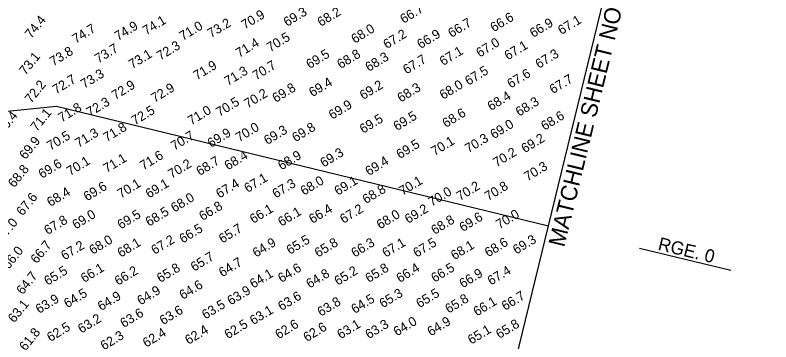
# Model space of a CAD drawing. Extents: x 401290 to 405690, y 1190598 to 1193998.
# Drawn here: x 404273 to 405078, y 1191942 to 1192291 of the extents above; entities that cross this region are included whole.
import ezdxf

# ---------------------------------------------------------------- set-up
doc = ezdxf.new("R2010")
doc.units = 0
for name, color, linetype in [('C-CHAN-POIT', 7, 'Continuous'), ('V-ALGN-TEXT', 7, 'Continuous'), ('V-ANNO-MATC', 7, 'Continuous'), ('V-ANNO-MATC-IDEN', 7, 'Continuous'), ('V-TOPO-SOUN', 7, 'Continuous')]:
    doc.layers.add(name, color=color, linetype=linetype)

msp = doc.modelspace()

# ---------------------------------------------------------------- linework, layer by layer
at = {"layer": 'C-CHAN-POIT'}
for p, q in [((402579.39, 1192009.5), (404317.15, 1192193.7)), ((404317.15, 1192193.7), (404840.85, 1192065.98))]:
    msp.add_line(p, q, dxfattribs=at)
at = {"layer": 'V-ALGN-TEXT'}
msp.add_line((404938, 1192042.28), (405035.16, 1192018.59), dxfattribs=at)
at = {"layer": 'V-ANNO-MATC'}
msp.add_line((404692.33, 1191456.98), (405077.78, 1193037.5), dxfattribs=at)

# ---------------------------------------------------------------- texts
at = {"layer": 'V-ALGN-TEXT'}
msp.add_text('RGE. 0', height=13.92, rotation=346.29456, dxfattribs=at).set_placement((404956.72, 1192040.59))
at = {"layer": 'V-ANNO-MATC-IDEN'}
msp.add_text('MATCHLINE SHEET NO. 025 STA. 6+00 EGMONT CUT-2', height=17.52, rotation=76.29456, dxfattribs=at).set_placement((404857.67, 1192042.53))
at = {"layer": 'V-TOPO-SOUN'}
for s, rotation, p in [('69.3 ', 31.2939, (404562.67, 1192278.04)), ('68.2 ', 31.2939, (404598.66, 1192278.04)), ('66.7 ', 31.2939, (404686.75, 1192281.29)), ('74.4 ', 51.05, (404290.2, 1192265.01)), ('74.1 ', 31.2939, (404412.67, 1192269.02)), ('70.9 ', 31.2939, (404517.69, 1192275.03)), ('66.6 ', 31.2939, (404782.75, 1192272.3)), ('67.1 ', 31.2939, (404854.77, 1192269.32)), ('74.7 ', 31.2939, (404337.67, 1192260.03)), ('74.9 ', 31.2939, (404382.69, 1192263.02)), ('71.0 ', 31.2939, (404451.68, 1192263.02)), ('73.2 ', 31.2939, (404481.67, 1192266.04)), ('68.0 ', 31.2939, (404634.69, 1192260.03)), ('66.7 ', 31.2939, (404737.77, 1192266.3)), ('66.9 ', 31.2939, (404824.78, 1192266.3)), ('70.5 ', 31.2939, (404544.66, 1192251.04)), ('67.2 ', 31.2939, (404668.77, 1192254.32)), ('66.9 ', 31.2939, (404704.77, 1192254.32)), ('71.4 ', 31.2939, (404511.69, 1192245.04)), ('67.0 ', 31.2939, (404767.76, 1192245.3)), ('73.8 ', 31.2939, (404313.69, 1192236.02)), ('73.7 ', 31.2939, (404361.69, 1192239.04)), ('72.3 ', 31.2939, (404427.67, 1192242.02)), ('67.1 ', 31.2939, (404728.78, 1192236.31)), ('67.1 ', 31.2939, (404797.78, 1192242.32)), ('73.1 ', 51.05, (404284.19, 1192226.04)), ('73.1 ', 31.2939, (404397.68, 1192233.03)), ('69.5 ', 31.2939, (404586.69, 1192233.03)), ('68.8 ', 31.2939, (404619.66, 1192233.03)), ('68.3 ', 31.2939, (404649.68, 1192230.05)), ('67.7 ', 31.2939, (404689.77, 1192227.32)), ('67.3 ', 31.2939, (404830.78, 1192233.29)), ('71.9 ', 31.2939, (404466.68, 1192221.02)), ('70.7 ', 31.2939, (404529.67, 1192221.02)), ('73.3 ', 31.2939, (404346.66, 1192212.03)), ('71.3 ', 31.2939, (404499.68, 1192215.02)), ('67.5 ', 31.2939, (404755.78, 1192215.31)), ('67.6 ', 31.2939, (404800.76, 1192212.3)), ('72.7 ', 31.2939, (404316.68, 1192206.03)), ('69.4 ', 31.2939, (404589.67, 1192203.04)), ('67.7 ', 31.2939, (404845.78, 1192206.29)), ('72.2 ', 51.05, (404290.2, 1192196.02)), ('72.9 ', 31.2939, (404379.67, 1192200.03)), ('72.9 ', 31.2939, (404421.66, 1192197.04)), ('69.8 ', 31.2939, (404550.66, 1192197.04)), ('69.2 ', 31.2939, (404643.68, 1192200.03)), ('68.3 ', 31.2939, (404683.77, 1192197.3)), ('68.0 ', 31.2939, (404728.78, 1192200.32)), ('70.2 ', 31.2939, (404520.68, 1192191.04)), ('68.4 ', 31.2939, (404779.77, 1192188.31)), ('72.3 ', 31.2939, (404352.67, 1192182.01)), ('70.5 ', 31.2939, (404490.69, 1192182.01)), ('69.9 ', 31.2939, (404610.67, 1192179.03)), ('68.3 ', 31.2939, (404809.75, 1192182.31)), ('71.8 ', 31.2939, (404322.68, 1192176.04)), ('72.5 ', 31.2939, (404400.66, 1192173.02)), ('71.0 ', 31.2939, (404460.67, 1192173.02)), ('68.6 ', 31.2939, (404731.77, 1192170.3)), ('70.4 ', 51.05, (404260.18, 1192163.01)), ('71.1 ', 51.05, (404296.2, 1192166.03)), ('69.5 ', 31.2939, (404643.68, 1192164.04)), ('69.5 ', 31.2939, (404679.67, 1192167.02)), ('68.6 ', 31.2939, (404836.75, 1192167.32)), ('71.8 ', 31.2939, (404370.68, 1192155.05)), ('70.0 ', 31.2939, (404511.69, 1192155.05)), ('69.8 ', 31.2939, (404571.66, 1192155.05)), ('69.0 ', 31.2939, (404782.75, 1192158.29)), ('70.5 ', 31.2939, (404310.67, 1192146.02)), ('71.3 ', 31.2939, (404340.69, 1192149.04)), ('70.7 ', 31.2939, (404442.69, 1192146.02)), ('69.9 ', 31.2939, (404481.67, 1192149.04)), ('69.3 ', 31.2939, (404541.68, 1192152.03)), ('69.9 ', 51.05, (404284.19, 1192136.01)), ('70.1 ', 31.2939, (404719.76, 1192140.32)), ('70.3 ', 31.2939, (404755.78, 1192143.3)), ('69.2 ', 31.2939, (404815.76, 1192143.3)), ('69.5 ', 31.2939, (404682.69, 1192137.03)), ('71.6 ', 31.2939, (404409.69, 1192125.03)), ('68.4 ', 31.2939, (404499.68, 1192125.03)), ('68.9 ', 31.2939, (404556.67, 1192125.03)), ('69.3 ', 31.2939, (404601.68, 1192128.04)), ('70.2 ', 31.2939, (404785.77, 1192128.31)), ('69.6 ', 31.2939, (404301.68, 1192116.04)), ('70.1 ', 31.2939, (404331.67, 1192119.02)), ('71.1 ', 31.2939, (404370.68, 1192122.04)), ('70.2 ', 31.2939, (404439.67, 1192116.04)), ('68.7 ', 31.2939, (404469.66, 1192119.02)), ('69.4 ', 31.2939, (404649.68, 1192119.02)), ('68.8 ', 51.05, (404272.19, 1192106.02)), ('70.3 ', 31.2939, (404818.77, 1192113.31)), ('67.1 ', 31.2939, (404520.68, 1192101.04)), ('69.6 ', 31.2939, (404349.68, 1192092.02)), ('70.1 ', 31.2939, (404385.67, 1192095.04)), ('69.1 ', 31.2939, (404415.69, 1192095.04)), ('67.4 ', 31.2939, (404490.69, 1192095.04)), ('67.3 ', 31.2939, (404550.66, 1192095.04)), ('68.0 ', 31.2939, (404580.68, 1192098.03)), ('69.1 ', 31.2939, (404616.67, 1192098.03)), ('70.1 ', 31.2939, (404685.67, 1192098.03)), ('70.2 ', 31.2939, (404746.76, 1192092.32)), ('70.8 ', 31.2939, (404776.78, 1192092.32)), ('68.4 ', 31.2939, (404310.67, 1192086.02)), ('68.8 ', 31.2939, (404646.66, 1192089.04)), ('70.0 ', 31.2939, (404716.77, 1192086.31)), ('67.6 ', 51.05, (404281.18, 1192076.04)), ('68.0 ', 31.2939, (404442.69, 1192080.05)), ('66.8 ', 31.2939, (404472.68, 1192071.02)), ('66.1 ', 31.2939, (404526.68, 1192068.04)), ('66.4 ', 31.2939, (404589.67, 1192068.04)), ('67.2 ', 31.2939, (404622.68, 1192068.04)), ('69.2 ', 31.2939, (404691.67, 1192068.04)), ('69.0 ', 31.2939, (404337.67, 1192062.03)), ('69.5 ', 31.2939, (404385.67, 1192062.03)), ('68.5 ', 31.2939, (404415.69, 1192065.02)), ('66.1 ', 31.2939, (404556.67, 1192065.02)), ('68.0 ', 31.2939, (404661.69, 1192062.03)), ('69.6 ', 31.2939, (404749.78, 1192059.31)), ('70.0 ', 31.2939, (404788.75, 1192062.3)), ('67.0 ', 51.05, (404260.18, 1192049.03)), ('67.8 ', 31.2939, (404307.69, 1192056.03)), ('68.8 ', 31.2939, (404719.76, 1192056.29)), ('66.5 ', 31.2939, (404451.68, 1192047.04)), ('65.7 ', 31.2939, (404493.68, 1192047.04)), ('68.0 ', 31.2939, (404355.68, 1192035.03)), ('67.2 ', 31.2939, (404421.66, 1192035.03)), ('65.5 ', 31.2939, (404565.69, 1192035.03)), ('69.3 ', 31.2939, (404806.77, 1192035.3)), ('66.7 ', 51.05, (404296.2, 1192025.02)), ('67.2 ', 31.2939, (404325.67, 1192029.03)), ('68.1 ', 31.2939, (404385.67, 1192032.01)), ('64.9 ', 31.2939, (404529.67, 1192032.01)), ('65.8 ', 31.2939, (404595.68, 1192032.01)), ('66.3 ', 31.2939, (404634.69, 1192032.01)), ('67.1 ', 31.2939, (404667.69, 1192032.01)), ('67.5 ', 31.2939, (404700.66, 1192032.01)), ('68.1 ', 31.2939, (404740.76, 1192029.32)), ('68.6 ', 31.2939, (404776.78, 1192032.31)), ('66.0 ', 51.05, (404266.18, 1192019.02)), ('65.7 ', 31.2939, (404463.69, 1192017.02)), ('64.7 ', 31.2939, (404493.68, 1192011.02)), ('65.5 ', 31.2939, (404307.69, 1192002.03)), ('66.1 ', 31.2939, (404346.66, 1192005.05)), ('66.2 ', 31.2939, (404382.69, 1192002.03)), ('65.8 ', 31.2939, (404427.67, 1192005.05)), ('64.6 ', 31.2939, (404556.67, 1192005.05)), ('65.2 ', 31.2939, (404616.67, 1192002.03)), ('65.8 ', 31.2939, (404649.68, 1192005.05)), ('66.4 ', 31.2939, (404682.69, 1192005.05)), ('66.5 ', 31.2939, (404719.76, 1192005.31)), ('67.4 ', 31.2939, (404779.77, 1192002.32)), ('64.7 ', 51.05, (404281.18, 1191992.01)), ('64.1 ', 31.2939, (404526.68, 1191999.04)), ('64.8 ', 31.2939, (404586.69, 1191999.04)), ('66.9 ', 31.2939, (404749.78, 1191999.3)), ('64.6 ', 31.2939, (404451.68, 1191987.03)), ('64.5 ', 31.2939, (404328.68, 1191978.05)), ('64.9 ', 31.2939, (404406.67, 1191981.03)), ('63.9 ', 31.2939, (404502.67, 1191981.03)), ('65.3 ', 31.2939, (404664.67, 1191978.05)), ('65.5 ', 31.2939, (404703.68, 1191978.05)), ('63.9 ', 31.2939, (404298.66, 1191972.04)), ('64.9 ', 31.2939, (404364.67, 1191975.03)), ('63.6 ', 31.2939, (404556.67, 1191975.03)), ('64.5 ', 31.2939, (404634.69, 1191972.04)), ('65.8 ', 31.2939, (404734.75, 1191972.3)), ('66.7 ', 31.2939, (404794.76, 1191975.32)), ('63.1 ', 51.05, (404272.19, 1191962.03)), ('63.5 ', 31.2939, (404475.66, 1191966.04)), ('63.8 ', 31.2939, (404598.66, 1191969.02)), ('66.1 ', 31.2939, (404764.77, 1191969.32)), ('63.6 ', 31.2939, (404388.69, 1191957.01)), ('63.6 ', 31.2939, (404430.68, 1191960.03)), ('63.1 ', 31.2939, (404526.68, 1191960.03)), ('63.2 ', 31.2939, (404343.68, 1191951.04)), ('62.5 ', 31.2939, (404499.68, 1191945.04)), ('62.6 ', 31.2939, (404553.68, 1191945.04)), ('64.0 ', 31.2939, (404679.67, 1191948.03)), ('64.9 ', 31.2939, (404715.69, 1191948.03)), ('62.5 ', 31.2939, (404310.67, 1191942.02)), ('62.4 ', 31.2939, (404457.69, 1191939.04)), ('62.6 ', 31.2939, (404583.67, 1191942.02)), ('63.1 ', 31.2939, (404619.66, 1191945.04)), ('63.3 ', 31.2939, (404649.68, 1191945.04)), ('65.1 ', 31.2939, (404758.77, 1191939.3)), ('65.8 ', 31.2939, (404788.75, 1191945.3)), ('61.8 ', 51.05, (404284.19, 1191932.01)), ('62.3 ', 31.2939, (404367.69, 1191933.03)), ('62.4 ', 31.2939, (404412.67, 1191936.02))]:
    msp.add_text(s, height=9.996, rotation=rotation, dxfattribs=at).set_placement(p)

doc.saveas('drawing.dxf')
